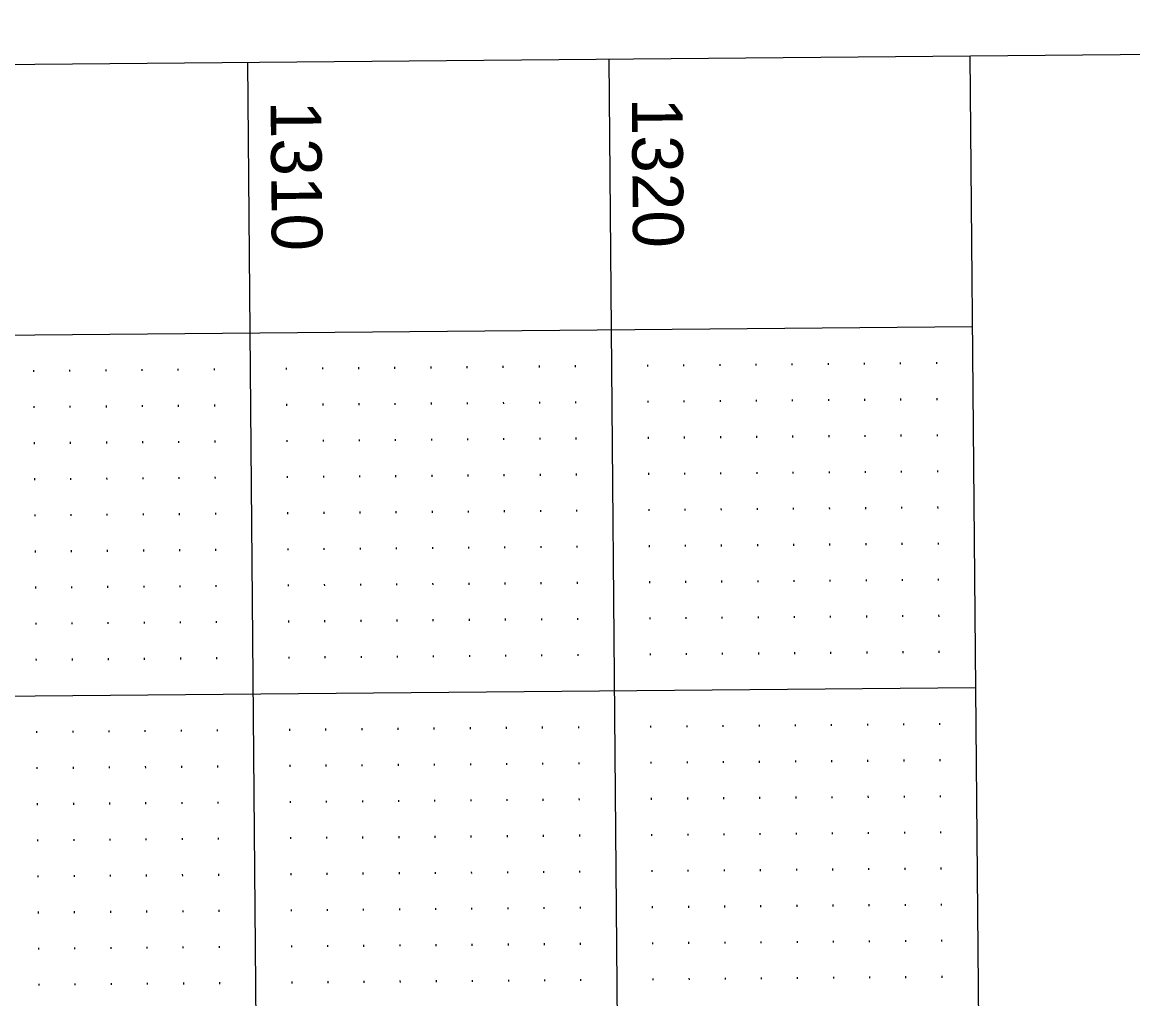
# Model space of a CAD drawing. Extents: x 2149873 to 2152007, y 140538 to 142349.
# Drawn here: x 2150344.5 to 2150498.3, y 142033.4 to 142168.7 of the extents above; entities that cross this region are included whole.
import ezdxf

# ---------------------------------------------------------------- set-up
doc = ezdxf.new("R2010")
doc.units = 0
for name, color, linetype in [('SHT_Plan_Profile_Sheet_Elev_Txt', 7, 'Continuous'), ('SHT_Profile_Grid_Major', 7, 'Continuous'), ('SHT_Profile_Grid_Minor', 7, 'Continuous'), ('SHT_Sheet_Border', 7, 'Continuous')]:
    doc.layers.add(name, color=color, linetype=linetype)

msp = doc.modelspace()

# ---------------------------------------------------------------- linework, layer by layer
at = {"layer": 'SHT_Profile_Grid_Major'}
for p, q in [((2150375.71, 142163.13), (2150389.5, 140588.19)), ((2150425.71, 142163.57), (2150439.49, 140588.63)), ((2149976.49, 142072.13), (2150476.47, 142076.51))]:
    msp.add_line(p, q, dxfattribs=at)
at = {"layer": 'SHT_Profile_Grid_Minor'}
for p, q in [((2150411.08, 142121.07), (2150411.08, 142120.82)), ((2150416.08, 142121.11), (2150416.08, 142120.86)), ((2150421.08, 142121.15), (2150421.08, 142120.9)), ((2150431.08, 142121.24), (2150431.08, 142120.99)), ((2150436.08, 142121.28), (2150436.08, 142121.03)), ((2150441.08, 142121.33), (2150441.08, 142121.08)), ((2150446.08, 142121.37), (2150446.08, 142121.12)), ((2150451.08, 142121.42), (2150451.08, 142121.17)), ((2150456.08, 142121.46), (2150456.08, 142121.21)), ((2150461.08, 142121.5), (2150461.08, 142121.25)), ((2150466.08, 142121.55), (2150466.08, 142121.3)), ((2150471.08, 142121.59), (2150471.08, 142121.34)), ((2150346.08, 142120.5), (2150346.08, 142120.25)), ((2150351.08, 142120.54), (2150351.08, 142120.29)), ((2150356.08, 142120.58), (2150356.08, 142120.33)), ((2150361.08, 142120.63), (2150361.08, 142120.38)), ((2150366.08, 142120.67), (2150366.08, 142120.42)), ((2150371.08, 142120.72), (2150371.08, 142120.47)), ((2150381.08, 142120.8), (2150381.08, 142120.55)), ((2150386.08, 142120.85), (2150386.08, 142120.6)), ((2150391.08, 142120.89), (2150391.08, 142120.64)), ((2150396.08, 142120.93), (2150396.08, 142120.68)), ((2150401.08, 142120.98), (2150401.08, 142120.73)), ((2150406.08, 142121.02), (2150406.08, 142120.77)), ((2150456.12, 142116.46), (2150456.12, 142116.21)), ((2150461.12, 142116.5), (2150461.12, 142116.25)), ((2150466.12, 142116.55), (2150466.12, 142116.3)), ((2150471.12, 142116.59), (2150471.12, 142116.34)), ((2150346.13, 142115.5), (2150346.13, 142115.25)), ((2150351.13, 142115.54), (2150351.13, 142115.29)), ((2150356.13, 142115.58), (2150356.13, 142115.33)), ((2150361.13, 142115.63), (2150361.13, 142115.38)), ((2150366.13, 142115.67), (2150366.13, 142115.42)), ((2150371.13, 142115.72), (2150371.13, 142115.47)), ((2150381.13, 142115.8), (2150381.13, 142115.55)), ((2150386.12, 142115.85), (2150386.13, 142115.6)), ((2150391.12, 142115.89), (2150391.13, 142115.64)), ((2150396.12, 142115.93), (2150396.13, 142115.68)), ((2150401.12, 142115.98), (2150401.13, 142115.73)), ((2150406.12, 142116.02), (2150406.13, 142115.77)), ((2150411.12, 142116.07), (2150411.13, 142115.82)), ((2150416.12, 142116.11), (2150416.13, 142115.86)), ((2150421.12, 142116.15), (2150421.13, 142115.9)), ((2150431.12, 142116.24), (2150431.13, 142115.99)), ((2150436.12, 142116.28), (2150436.13, 142116.03)), ((2150441.12, 142116.33), (2150441.13, 142116.08)), ((2150446.12, 142116.37), (2150446.12, 142116.12)), ((2150451.12, 142116.42), (2150451.12, 142116.17)), ((2150346.17, 142110.5), (2150346.17, 142110.25)), ((2150351.17, 142110.54), (2150351.17, 142110.29)), ((2150356.17, 142110.58), (2150356.17, 142110.33)), ((2150361.17, 142110.63), (2150361.17, 142110.38)), ((2150366.17, 142110.67), (2150366.17, 142110.42)), ((2150371.17, 142110.72), (2150371.17, 142110.47)), ((2150381.17, 142110.8), (2150381.17, 142110.55)), ((2150386.17, 142110.85), (2150386.17, 142110.6)), ((2150391.17, 142110.89), (2150391.17, 142110.64)), ((2150396.17, 142110.93), (2150396.17, 142110.68)), ((2150401.17, 142110.98), (2150401.17, 142110.73)), ((2150406.17, 142111.02), (2150406.17, 142110.77)), ((2150411.17, 142111.07), (2150411.17, 142110.82)), ((2150416.17, 142111.11), (2150416.17, 142110.86)), ((2150421.17, 142111.15), (2150421.17, 142110.9)), ((2150431.17, 142111.24), (2150431.17, 142110.99)), ((2150436.17, 142111.28), (2150436.17, 142111.03)), ((2150441.17, 142111.33), (2150441.17, 142111.08)), ((2150446.17, 142111.37), (2150446.17, 142111.12)), ((2150451.17, 142111.42), (2150451.17, 142111.17)), ((2150456.17, 142111.46), (2150456.17, 142111.21)), ((2150461.17, 142111.5), (2150461.17, 142111.25)), ((2150466.17, 142111.55), (2150466.17, 142111.3)), ((2150471.17, 142111.59), (2150471.17, 142111.34)), ((2150366.21, 142105.67), (2150366.22, 142105.42)), ((2150371.21, 142105.72), (2150371.22, 142105.47)), ((2150381.21, 142105.8), (2150381.21, 142105.55)), ((2150386.21, 142105.85), (2150386.21, 142105.6)), ((2150391.21, 142105.89), (2150391.21, 142105.64)), ((2150396.21, 142105.93), (2150396.21, 142105.68)), ((2150401.21, 142105.98), (2150401.21, 142105.73)), ((2150406.21, 142106.02), (2150406.21, 142105.77)), ((2150411.21, 142106.07), (2150411.21, 142105.82)), ((2150416.21, 142106.11), (2150416.21, 142105.86)), ((2150421.21, 142106.15), (2150421.21, 142105.9)), ((2150431.21, 142106.24), (2150431.21, 142105.99)), ((2150436.21, 142106.28), (2150436.21, 142106.03)), ((2150441.21, 142106.33), (2150441.21, 142106.08)), ((2150446.21, 142106.37), (2150446.21, 142106.12)), ((2150451.21, 142106.42), (2150451.21, 142106.17)), ((2150456.21, 142106.46), (2150456.21, 142106.21)), ((2150461.21, 142106.5), (2150461.21, 142106.25)), ((2150466.21, 142106.55), (2150466.21, 142106.3)), ((2150471.21, 142106.59), (2150471.21, 142106.34)), ((2150346.21, 142105.5), (2150346.22, 142105.25)), ((2150351.21, 142105.54), (2150351.22, 142105.29)), ((2150356.21, 142105.58), (2150356.22, 142105.33)), ((2150361.21, 142105.63), (2150361.22, 142105.38)), ((2150411.26, 142101.07), (2150411.26, 142100.82)), ((2150416.26, 142101.11), (2150416.26, 142100.86)), ((2150421.25, 142101.15), (2150421.26, 142100.9)), ((2150431.25, 142101.24), (2150431.26, 142100.99)), ((2150436.25, 142101.28), (2150436.26, 142101.03)), ((2150441.25, 142101.33), (2150441.26, 142101.08)), ((2150446.25, 142101.37), (2150446.26, 142101.12)), ((2150451.25, 142101.42), (2150451.26, 142101.17)), ((2150456.25, 142101.46), (2150456.26, 142101.21)), ((2150461.25, 142101.5), (2150461.26, 142101.25)), ((2150466.25, 142101.55), (2150466.26, 142101.3)), ((2150471.25, 142101.59), (2150471.26, 142101.34)), ((2150346.26, 142100.5), (2150346.26, 142100.25)), ((2150351.26, 142100.54), (2150351.26, 142100.29)), ((2150356.26, 142100.58), (2150356.26, 142100.33)), ((2150361.26, 142100.63), (2150361.26, 142100.38)), ((2150366.26, 142100.67), (2150366.26, 142100.42)), ((2150371.26, 142100.72), (2150371.26, 142100.47)), ((2150381.26, 142100.8), (2150381.26, 142100.55)), ((2150386.26, 142100.85), (2150386.26, 142100.6)), ((2150391.26, 142100.89), (2150391.26, 142100.64)), ((2150396.26, 142100.93), (2150396.26, 142100.68)), ((2150401.26, 142100.98), (2150401.26, 142100.73)), ((2150406.26, 142101.02), (2150406.26, 142100.77)), ((2150456.3, 142096.46), (2150456.3, 142096.21)), ((2150461.3, 142096.5), (2150461.3, 142096.25)), ((2150466.3, 142096.55), (2150466.3, 142096.3)), ((2150471.3, 142096.59), (2150471.3, 142096.34)), ((2150346.3, 142095.5), (2150346.3, 142095.25)), ((2150351.3, 142095.54), (2150351.3, 142095.29)), ((2150356.3, 142095.58), (2150356.3, 142095.33)), ((2150361.3, 142095.63), (2150361.3, 142095.38)), ((2150366.3, 142095.67), (2150366.3, 142095.42)), ((2150371.3, 142095.72), (2150371.3, 142095.47)), ((2150381.3, 142095.8), (2150381.3, 142095.55)), ((2150386.3, 142095.85), (2150386.3, 142095.6)), ((2150391.3, 142095.89), (2150391.3, 142095.64)), ((2150396.3, 142095.93), (2150396.3, 142095.68)), ((2150401.3, 142095.98), (2150401.3, 142095.73)), ((2150406.3, 142096.02), (2150406.3, 142095.77)), ((2150411.3, 142096.07), (2150411.3, 142095.82)), ((2150416.3, 142096.11), (2150416.3, 142095.86)), ((2150421.3, 142096.15), (2150421.3, 142095.9)), ((2150431.3, 142096.24), (2150431.3, 142095.99)), ((2150436.3, 142096.29), (2150436.3, 142096.04)), ((2150441.3, 142096.33), (2150441.3, 142096.08)), ((2150446.3, 142096.37), (2150446.3, 142096.12)), ((2150451.3, 142096.42), (2150451.3, 142096.17)), ((2150346.35, 142090.5), (2150346.35, 142090.25)), ((2150351.35, 142090.54), (2150351.35, 142090.29)), ((2150356.34, 142090.59), (2150356.35, 142090.34)), ((2150361.34, 142090.63), (2150361.35, 142090.38)), ((2150366.34, 142090.67), (2150366.35, 142090.42)), ((2150371.34, 142090.72), (2150371.35, 142090.47)), ((2150381.34, 142090.8), (2150381.35, 142090.55)), ((2150386.34, 142090.85), (2150386.35, 142090.6)), ((2150391.34, 142090.89), (2150391.35, 142090.64)), ((2150396.34, 142090.94), (2150396.35, 142090.69)), ((2150401.34, 142090.98), (2150401.35, 142090.73)), ((2150406.34, 142091.02), (2150406.35, 142090.77)), ((2150411.34, 142091.07), (2150411.34, 142090.82)), ((2150416.34, 142091.11), (2150416.34, 142090.86)), ((2150421.34, 142091.15), (2150421.34, 142090.9)), ((2150431.34, 142091.24), (2150431.34, 142090.99)), ((2150436.34, 142091.29), (2150436.34, 142091.04)), ((2150441.34, 142091.33), (2150441.34, 142091.08)), ((2150446.34, 142091.37), (2150446.34, 142091.12)), ((2150451.34, 142091.42), (2150451.34, 142091.17)), ((2150456.34, 142091.46), (2150456.34, 142091.21)), ((2150461.34, 142091.5), (2150461.34, 142091.25)), ((2150466.34, 142091.55), (2150466.34, 142091.3)), ((2150471.34, 142091.59), (2150471.34, 142091.34)), ((2150371.39, 142085.72), (2150371.39, 142085.47)), ((2150381.39, 142085.8), (2150381.39, 142085.55)), ((2150386.39, 142085.85), (2150386.39, 142085.6)), ((2150391.39, 142085.89), (2150391.39, 142085.64)), ((2150396.39, 142085.94), (2150396.39, 142085.69)), ((2150401.39, 142085.98), (2150401.39, 142085.73)), ((2150406.39, 142086.02), (2150406.39, 142085.77)), ((2150411.39, 142086.07), (2150411.39, 142085.82)), ((2150416.39, 142086.11), (2150416.39, 142085.86)), ((2150421.39, 142086.15), (2150421.39, 142085.9)), ((2150431.39, 142086.24), (2150431.39, 142085.99)), ((2150436.39, 142086.29), (2150436.39, 142086.04)), ((2150441.39, 142086.33), (2150441.39, 142086.08)), ((2150446.39, 142086.37), (2150446.39, 142086.12)), ((2150451.39, 142086.42), (2150451.39, 142086.17)), ((2150456.38, 142086.46), (2150456.39, 142086.21)), ((2150461.38, 142086.5), (2150461.39, 142086.25)), ((2150466.38, 142086.55), (2150466.39, 142086.3)), ((2150471.38, 142086.59), (2150471.39, 142086.34)), ((2150346.39, 142085.5), (2150346.39, 142085.25)), ((2150351.39, 142085.54), (2150351.39, 142085.29)), ((2150356.39, 142085.59), (2150356.39, 142085.34)), ((2150361.39, 142085.63), (2150361.39, 142085.38)), ((2150366.39, 142085.67), (2150366.39, 142085.42)), ((2150416.43, 142081.11), (2150416.43, 142080.86)), ((2150421.43, 142081.15), (2150421.43, 142080.9)), ((2150431.43, 142081.24), (2150431.43, 142080.99)), ((2150436.43, 142081.29), (2150436.43, 142081.04)), ((2150441.43, 142081.33), (2150441.43, 142081.08)), ((2150446.43, 142081.37), (2150446.43, 142081.12)), ((2150451.43, 142081.42), (2150451.43, 142081.17)), ((2150456.43, 142081.46), (2150456.43, 142081.21)), ((2150461.43, 142081.5), (2150461.43, 142081.25)), ((2150466.43, 142081.55), (2150466.43, 142081.3)), ((2150471.43, 142081.59), (2150471.43, 142081.34)), ((2150346.43, 142080.5), (2150346.44, 142080.25)), ((2150351.43, 142080.54), (2150351.43, 142080.29)), ((2150356.43, 142080.59), (2150356.43, 142080.34)), ((2150361.43, 142080.63), (2150361.43, 142080.38)), ((2150366.43, 142080.67), (2150366.43, 142080.42)), ((2150371.43, 142080.72), (2150371.43, 142080.47)), ((2150381.43, 142080.8), (2150381.43, 142080.55)), ((2150386.43, 142080.85), (2150386.43, 142080.6)), ((2150391.43, 142080.89), (2150391.43, 142080.64)), ((2150396.43, 142080.94), (2150396.43, 142080.69)), ((2150401.43, 142080.98), (2150401.43, 142080.73)), ((2150406.43, 142081.02), (2150406.43, 142080.77)), ((2150411.43, 142081.07), (2150411.43, 142080.82)), ((2150346.52, 142070.5), (2150346.52, 142070.25)), ((2150351.52, 142070.54), (2150351.52, 142070.29)), ((2150356.52, 142070.59), (2150356.52, 142070.34)), ((2150361.52, 142070.63), (2150361.52, 142070.38)), ((2150366.52, 142070.67), (2150366.52, 142070.42)), ((2150371.52, 142070.72), (2150371.52, 142070.47)), ((2150381.52, 142070.8), (2150381.52, 142070.55)), ((2150386.52, 142070.85), (2150386.52, 142070.6)), ((2150391.52, 142070.89), (2150391.52, 142070.64)), ((2150396.52, 142070.94), (2150396.52, 142070.69)), ((2150401.52, 142070.98), (2150401.52, 142070.73)), ((2150406.52, 142071.02), (2150406.52, 142070.77)), ((2150411.52, 142071.07), (2150411.52, 142070.82)), ((2150416.52, 142071.11), (2150416.52, 142070.86)), ((2150421.52, 142071.15), (2150421.52, 142070.9)), ((2150431.52, 142071.24), (2150431.52, 142070.99)), ((2150436.52, 142071.29), (2150436.52, 142071.04)), ((2150441.52, 142071.33), (2150441.52, 142071.08)), ((2150446.52, 142071.37), (2150446.52, 142071.12)), ((2150451.52, 142071.42), (2150451.52, 142071.17)), ((2150456.52, 142071.46), (2150456.52, 142071.21)), ((2150461.52, 142071.5), (2150461.52, 142071.25)), ((2150466.52, 142071.55), (2150466.52, 142071.3)), ((2150471.52, 142071.59), (2150471.52, 142071.34)), ((2150371.56, 142065.72), (2150371.57, 142065.47)), ((2150381.56, 142065.8), (2150381.56, 142065.55)), ((2150386.56, 142065.85), (2150386.56, 142065.6)), ((2150391.56, 142065.89), (2150391.56, 142065.64)), ((2150396.56, 142065.94), (2150396.56, 142065.69)), ((2150401.56, 142065.98), (2150401.56, 142065.73)), ((2150406.56, 142066.02), (2150406.56, 142065.77)), ((2150411.56, 142066.07), (2150411.56, 142065.82)), ((2150416.56, 142066.11), (2150416.56, 142065.86)), ((2150421.56, 142066.15), (2150421.56, 142065.9)), ((2150431.56, 142066.24), (2150431.56, 142065.99)), ((2150436.56, 142066.29), (2150436.56, 142066.04)), ((2150441.56, 142066.33), (2150441.56, 142066.08)), ((2150446.56, 142066.37), (2150446.56, 142066.12)), ((2150451.56, 142066.42), (2150451.56, 142066.17)), ((2150456.56, 142066.46), (2150456.56, 142066.21)), ((2150461.56, 142066.51), (2150461.56, 142066.26)), ((2150466.56, 142066.55), (2150466.56, 142066.3)), ((2150471.56, 142066.59), (2150471.56, 142066.34)), ((2150346.56, 142065.5), (2150346.57, 142065.25)), ((2150351.56, 142065.54), (2150351.57, 142065.29)), ((2150356.56, 142065.59), (2150356.57, 142065.34)), ((2150361.56, 142065.63), (2150361.57, 142065.38)), ((2150366.56, 142065.67), (2150366.57, 142065.42)), ((2150416.61, 142061.11), (2150416.61, 142060.86)), ((2150421.6, 142061.16), (2150421.61, 142060.91)), ((2150431.6, 142061.24), (2150431.61, 142060.99)), ((2150436.6, 142061.29), (2150436.61, 142061.04)), ((2150441.6, 142061.33), (2150441.61, 142061.08)), ((2150446.6, 142061.37), (2150446.61, 142061.12)), ((2150451.6, 142061.42), (2150451.61, 142061.17)), ((2150456.6, 142061.46), (2150456.61, 142061.21)), ((2150461.6, 142061.51), (2150461.61, 142061.26)), ((2150466.6, 142061.55), (2150466.61, 142061.3)), ((2150471.6, 142061.59), (2150471.61, 142061.34)), ((2150346.61, 142060.5), (2150346.61, 142060.25)), ((2150351.61, 142060.54), (2150351.61, 142060.29)), ((2150356.61, 142060.59), (2150356.61, 142060.34)), ((2150361.61, 142060.63), (2150361.61, 142060.38)), ((2150366.61, 142060.67), (2150366.61, 142060.42)), ((2150371.61, 142060.72), (2150371.61, 142060.47)), ((2150381.61, 142060.8), (2150381.61, 142060.55)), ((2150386.61, 142060.85), (2150386.61, 142060.6)), ((2150391.61, 142060.89), (2150391.61, 142060.64)), ((2150396.61, 142060.94), (2150396.61, 142060.69)), ((2150401.61, 142060.98), (2150401.61, 142060.73)), ((2150406.61, 142061.02), (2150406.61, 142060.77)), ((2150411.61, 142061.07), (2150411.61, 142060.82)), ((2150461.65, 142056.51), (2150461.65, 142056.26)), ((2150466.65, 142056.55), (2150466.65, 142056.3)), ((2150471.65, 142056.59), (2150471.65, 142056.34)), ((2150346.65, 142055.5), (2150346.65, 142055.25)), ((2150351.65, 142055.54), (2150351.65, 142055.29)), ((2150356.65, 142055.59), (2150356.65, 142055.34)), ((2150361.65, 142055.63), (2150361.65, 142055.38)), ((2150366.65, 142055.67), (2150366.65, 142055.42)), ((2150371.65, 142055.72), (2150371.65, 142055.47)), ((2150381.65, 142055.81), (2150381.65, 142055.56)), ((2150386.65, 142055.85), (2150386.65, 142055.6)), ((2150391.65, 142055.89), (2150391.65, 142055.64)), ((2150396.65, 142055.94), (2150396.65, 142055.69)), ((2150401.65, 142055.98), (2150401.65, 142055.73)), ((2150406.65, 142056.02), (2150406.65, 142055.77)), ((2150411.65, 142056.07), (2150411.65, 142055.82)), ((2150416.65, 142056.11), (2150416.65, 142055.86)), ((2150421.65, 142056.16), (2150421.65, 142055.91)), ((2150431.65, 142056.24), (2150431.65, 142055.99)), ((2150436.65, 142056.29), (2150436.65, 142056.04)), ((2150441.65, 142056.33), (2150441.65, 142056.08)), ((2150446.65, 142056.37), (2150446.65, 142056.12)), ((2150451.65, 142056.42), (2150451.65, 142056.17)), ((2150456.65, 142056.46), (2150456.65, 142056.21)), ((2150346.7, 142050.5), (2150346.7, 142050.25)), ((2150351.7, 142050.54), (2150351.7, 142050.29)), ((2150356.7, 142050.59), (2150356.7, 142050.34)), ((2150361.69, 142050.63), (2150361.7, 142050.38)), ((2150366.69, 142050.67), (2150366.7, 142050.42)), ((2150371.69, 142050.72), (2150371.7, 142050.47)), ((2150381.69, 142050.81), (2150381.7, 142050.56)), ((2150386.69, 142050.85), (2150386.7, 142050.6)), ((2150391.69, 142050.89), (2150391.7, 142050.64)), ((2150396.69, 142050.94), (2150396.7, 142050.69)), ((2150401.69, 142050.98), (2150401.7, 142050.73)), ((2150406.69, 142051.02), (2150406.7, 142050.77)), ((2150411.69, 142051.07), (2150411.7, 142050.82)), ((2150416.69, 142051.11), (2150416.69, 142050.86)), ((2150421.69, 142051.16), (2150421.69, 142050.91)), ((2150431.69, 142051.24), (2150431.69, 142050.99)), ((2150436.69, 142051.29), (2150436.69, 142051.04)), ((2150441.69, 142051.33), (2150441.69, 142051.08)), ((2150446.69, 142051.37), (2150446.69, 142051.12)), ((2150451.69, 142051.42), (2150451.69, 142051.17)), ((2150456.69, 142051.46), (2150456.69, 142051.21)), ((2150461.69, 142051.51), (2150461.69, 142051.26)), ((2150466.69, 142051.55), (2150466.69, 142051.3)), ((2150471.69, 142051.59), (2150471.69, 142051.34)), ((2150371.74, 142045.72), (2150371.74, 142045.47)), ((2150381.74, 142045.81), (2150381.74, 142045.56)), ((2150386.74, 142045.85), (2150386.74, 142045.6)), ((2150391.74, 142045.89), (2150391.74, 142045.64)), ((2150396.74, 142045.94), (2150396.74, 142045.69)), ((2150401.74, 142045.98), (2150401.74, 142045.73)), ((2150406.74, 142046.02), (2150406.74, 142045.77)), ((2150411.74, 142046.07), (2150411.74, 142045.82)), ((2150416.74, 142046.11), (2150416.74, 142045.86)), ((2150421.74, 142046.16), (2150421.74, 142045.91)), ((2150431.74, 142046.24), (2150431.74, 142045.99)), ((2150436.74, 142046.29), (2150436.74, 142046.04)), ((2150441.74, 142046.33), (2150441.74, 142046.08)), ((2150446.74, 142046.37), (2150446.74, 142046.12)), ((2150451.74, 142046.42), (2150451.74, 142046.17)), ((2150456.73, 142046.46), (2150456.74, 142046.21)), ((2150461.73, 142046.51), (2150461.74, 142046.26)), ((2150466.73, 142046.55), (2150466.74, 142046.3)), ((2150471.73, 142046.59), (2150471.74, 142046.34)), ((2150346.74, 142045.5), (2150346.74, 142045.25)), ((2150351.74, 142045.54), (2150351.74, 142045.29)), ((2150356.74, 142045.59), (2150356.74, 142045.34)), ((2150361.74, 142045.63), (2150361.74, 142045.38)), ((2150366.74, 142045.67), (2150366.74, 142045.42)), ((2150416.78, 142041.11), (2150416.78, 142040.86)), ((2150421.78, 142041.16), (2150421.78, 142040.91)), ((2150431.78, 142041.24), (2150431.78, 142040.99)), ((2150436.78, 142041.29), (2150436.78, 142041.04)), ((2150441.78, 142041.33), (2150441.78, 142041.08)), ((2150446.78, 142041.37), (2150446.78, 142041.12)), ((2150451.78, 142041.42), (2150451.78, 142041.17)), ((2150456.78, 142041.46), (2150456.78, 142041.21)), ((2150461.78, 142041.51), (2150461.78, 142041.26)), ((2150466.78, 142041.55), (2150466.78, 142041.3)), ((2150471.78, 142041.59), (2150471.78, 142041.34)), ((2150346.78, 142040.5), (2150346.79, 142040.25)), ((2150351.78, 142040.54), (2150351.78, 142040.29)), ((2150356.78, 142040.59), (2150356.78, 142040.34)), ((2150361.78, 142040.63), (2150361.78, 142040.38)), ((2150366.78, 142040.67), (2150366.78, 142040.42)), ((2150371.78, 142040.72), (2150371.78, 142040.47)), ((2150381.78, 142040.81), (2150381.78, 142040.56)), ((2150386.78, 142040.85), (2150386.78, 142040.6)), ((2150391.78, 142040.89), (2150391.78, 142040.64)), ((2150396.78, 142040.94), (2150396.78, 142040.69)), ((2150401.78, 142040.98), (2150401.78, 142040.73)), ((2150406.78, 142041.02), (2150406.78, 142040.77)), ((2150411.78, 142041.07), (2150411.78, 142040.82)), ((2150461.82, 142036.51), (2150461.82, 142036.26)), ((2150466.82, 142036.55), (2150466.82, 142036.3)), ((2150471.82, 142036.59), (2150471.82, 142036.34)), ((2150346.83, 142035.5), (2150346.83, 142035.25)), ((2150351.83, 142035.54), (2150351.83, 142035.29)), ((2150356.83, 142035.59), (2150356.83, 142035.34)), ((2150361.83, 142035.63), (2150361.83, 142035.38)), ((2150366.83, 142035.67), (2150366.83, 142035.42)), ((2150371.83, 142035.72), (2150371.83, 142035.47)), ((2150381.83, 142035.81), (2150381.83, 142035.56)), ((2150386.83, 142035.85), (2150386.83, 142035.6)), ((2150391.82, 142035.89), (2150391.83, 142035.64)), ((2150396.82, 142035.94), (2150396.83, 142035.69)), ((2150401.82, 142035.98), (2150401.83, 142035.73)), ((2150406.82, 142036.02), (2150406.83, 142035.77)), ((2150411.82, 142036.07), (2150411.83, 142035.82)), ((2150416.82, 142036.11), (2150416.83, 142035.86)), ((2150421.82, 142036.16), (2150421.83, 142035.91)), ((2150431.82, 142036.24), (2150431.83, 142035.99)), ((2150436.82, 142036.29), (2150436.83, 142036.04)), ((2150441.82, 142036.33), (2150441.83, 142036.08)), ((2150446.82, 142036.37), (2150446.83, 142036.12)), ((2150451.82, 142036.42), (2150451.82, 142036.17)), ((2150456.82, 142036.46), (2150456.82, 142036.21))]:
    msp.add_line(p, q, dxfattribs=at)
at = {"layer": 'SHT_Sheet_Border'}
for p, q in [((2150475.71, 142164.01), (2150489.49, 140589.07)), ((2149976.05, 142122.13), (2150476.04, 142126.51))]:
    msp.add_line(p, q, dxfattribs=at)
msp.add_lwpolyline([(2151008.19, 142168.67), (2151021.97, 140593.73), (2149972.01, 140584.54), (2149958.23, 142159.48)], close=True, dxfattribs=at)

# ---------------------------------------------------------------- texts
at = {"layer": 'SHT_Plan_Profile_Sheet_Elev_Txt'}
for s, p in [('1310', (2150378.91, 142157.77)), ('1320', (2150428.91, 142158.2))]:
    msp.add_text(s, height=7, rotation=270.5015, dxfattribs=at).set_placement(p)

doc.saveas('drawing.dxf')
